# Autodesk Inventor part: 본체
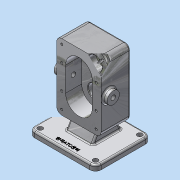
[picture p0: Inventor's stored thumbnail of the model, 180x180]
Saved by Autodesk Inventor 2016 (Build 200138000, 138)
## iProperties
Created: 2020-04
Part Number: 본체
Material: 알루미늄 6061
Document SubType Name: Modeling
Designer: MIRAE
Density: 2.7 g/cm^3
Appearance: 알루미늄 - 평지
Mass: 1472.54 g
Surface Area: 818.394 cm^2
Volume: 545.387 cm^3
Author: MIRAE
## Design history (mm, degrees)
sketch "스케치1"
  geometry: L1 (-60, -44)-(60, -44); L2 (60, -44)-(60, 56); L3 (60, 56)-(-60, 56); L4 (-60, 56)-(-60, -44); L5 (-60, -44)-(60, 56); L6 (60, -44)-(-60, 56); 1 further point
  constraints: 12 end point, 2 parallel, 1 horizontal, 1 perpendicular
  dimensions: "d0" = 120 distance of L3.end L2.end; "d1" = 100 distance of L2.end L1.end; "d62" = 60 distance from line of point (0, 0) L4; "d63" = 56 distance from line of point (0, 0) L3
extrude "돌출1" new body sketch "스케치1" distance "d2" = 10; taper "d3" = 0 deg
sketch "스케치2"
  geometry: L1 (40, 30)-(-40, 30); L2 (-40, 30)-(-40, 150); L3 (-40, 150)-(40, 150); L4 (40, 150)-(40, 30); L5 (40, 30)-(-40, 150); L6 (-40, 30)-(40, 150); L7 (60, 0)-(-60, 0) reference; 4 further points
  constraints: 12 end point, 4 midpoint, 2 parallel, 1 horizontal, 1 perpendicular, 1 vertical alignment
  dimensions: "d4" = 80 distance of L2.end L3.end; "d5" = 120 distance of L1.end L2.end; "d6" = 150 distance between parallel lines of L7 L3
extrude "돌출2" join sketch "스케치2" distance "d7" = 39; taper "d9" = 0 deg; dims "d8" = 14, "d10" = 0
sketch "스케치3"
  geometry: L1 (56, 0)-(-44, 0) reference; C1 r 11 at (0, 90); 1 further point
  constraints: 1 centre point, 1 vertical alignment
  dimensions: "d11" = 22 diameter of C1; "d12" = 90 distance from line of L1 C1.centre
extrude "돌출3" join sketch "스케치3" stored distance "d13" = 96; taper "d14" = 0 deg
sketch "스케치4"
  geometry: L1 (60, 0)-(-60, 0) reference; C1 r 19 at (0, -112); 2 further points
  constraints: 1 centre point, 1 midpoint, 1 vertical alignment
  dimensions: "d15" = 38 diameter of C1; "d16" = 112 distance from line of L1 C1.centre
extrude "돌출4" join sketch "스케치4" distance "d17" = 17; taper "d18" = 0 deg
sketch "스케치5"
  geometry: L1 (0, 112)-(0, 68); L2 (-24, 112)-(-24, 68); L3 (24, 68)-(24, 112); C1 r 19 at (0, 112) reference; A1 r 24 centre (0, 112) between (24, 112) and (-24, 112); A2 r 24 centre (0, 68) between (-24, 68) and (24, 68); 2 further points
  constraints: 8 end point, 4 point on circle, 4 tangent, 2 centre point, 1 midpoint, 1 parallel, 1 vertical
  dimensions: "d19" = 24 radius of A2; "d20" = 44 distance of L1.start L1.end
extrude "돌출5" cut sketch "스케치5" distance "d21" = 29; taper "d22" = 0 deg
sketch "스케치6"
  geometry: A1 r 24 centre (0, 68) between (-24, 68) and (24, 68) reference; A2 r 24 centre (0, 112) between (24, 112) and (-24, 112) reference; 3 further points
  constraints: 2 coincident
hole "구멍1" sketch "스케치6" at (0, 68), (0, 112) diameter "d23" = 25; stored, may be unused: countersink angle "d27" = 90 deg, drill point angle "d29" = 0 deg; dims "d24" = 6, "d25" = 4, "d26" = 2, "d28" = 15
hole "구멍2" diameter "d32" = 17; stored, may be unused: countersink angle "d36" = 90 deg, drill point angle "d38" = 0 deg; dims "d30" = 10, "d31" = 10, "d33" = 6, "d34" = 28, "d35" = 7.3, "d37" = 15
hole "구멍3" diameter "d41" = 8.376; stored, may be unused: countersink angle "d45" = 90 deg, drill point angle "d47" = 0 deg; dims "d39" = 10, "d40" = 10, "d42" = 20, "d43" = 28, "d44" = 7.3, "d46" = 27.3
fillet "모깎기1" dims "d48" = 10
sketch "스케치7"
  geometry: A1 r 10 centre (50, 46) between (60, 46) and (50, 56) reference; A2 r 10 centre (50, -34) between (50, -44) and (60, -34) reference; A3 r 10 centre (-50, -34) between (-60, -34) and (-50, -44) reference; A4 r 10 centre (-50, 46) between (-50, 56) and (-60, 46) reference; 5 further points
  constraints: 4 coincident
hole "구멍4" sketch "스케치7" at (50, 46), (50, -34), (-50, -34), (-50, 46) diameter "d49" = 9; stored, may be unused: countersink angle "d53" = 90 deg, drill point angle "d55" = 0 deg; dims "d50" = 20, "d51" = 28, "d52" = 7.3, "d54" = 27.3
sketch "스케치8"
  geometry: L1 (39, 30)-(-14, 30) reference; L2 (-2.453, 30)-(-14, 10); L3 (-34, 10)-(46, 10) reference; L4 (39, 10)-(27.453, 30); L5 (-2.453, 30)-(27.453, 30); L6 (-14, 10)-(39, 10); L7 (56, 10)-(56, 0) reference; 1 further point
  constraints: 8 end point, 4 point on line, 2 collinear
  dimensions: "d56" = 60 deg angle of L3 L4; "d57" = 60 deg angle of L3 L2; "d58" = 17 distance from line of L7 L4.start; "d59" = 53 distance of L2.end L4.start
extrude "돌출6" join sketch "스케치8" stored distance "d60" = 48; taper "d61" = 0 deg
sketch "스케치9"
  geometry: L1 (-60, 46)-(-60, -34) reference; L2 (-50, -44)-(50, -44) reference; 2 further points
  constraints: 1 other
  dimensions: "d64" = 60 distance from line of L1 point (0, -34); "d65" = 10 distance from line of L2 point (0, -34)
feature "엠보싱1" sketch "스케치9" dims "d0" = 120, "d1" = 100, "d62" = 60, "d63" = 56, "d66" = 0.5, "d67" = 0
chamfer "모따기1" distance "d68" = 1; stored, may be unused: second distance "d69" = 2, angle "d70" = 45 deg
fillet "모깎기2" dims "d71" = 9
hole "구멍5" diameter "d74" = 4.134; stored, may be unused: countersink angle "d78" = 90 deg, drill point angle "d80" = 118 deg; dims "d75" = 10, "d76" = 28, "d77" = 7.3, "d79" = 12, "d98" = 10, "d99" = 10
chamfer "모따기2" distance "d92" = 0.7; stored, may be unused: second distance "d93" = 2, angle "d94" = 30 deg
fillet "모깎기3" dims "d95" = 0.5, "d96" = 3
fillet "모깎기4" dims "d97" = 3
feature "분할1"
node "솔리드1"
mirror "대칭1"
pattern_linear "직사각형 패턴1" dims "d85" = 29
pattern_linear "직사각형 패턴2" dims "d88" = 102
pattern_linear "직사각형 패턴3" dims "d91" = 73
